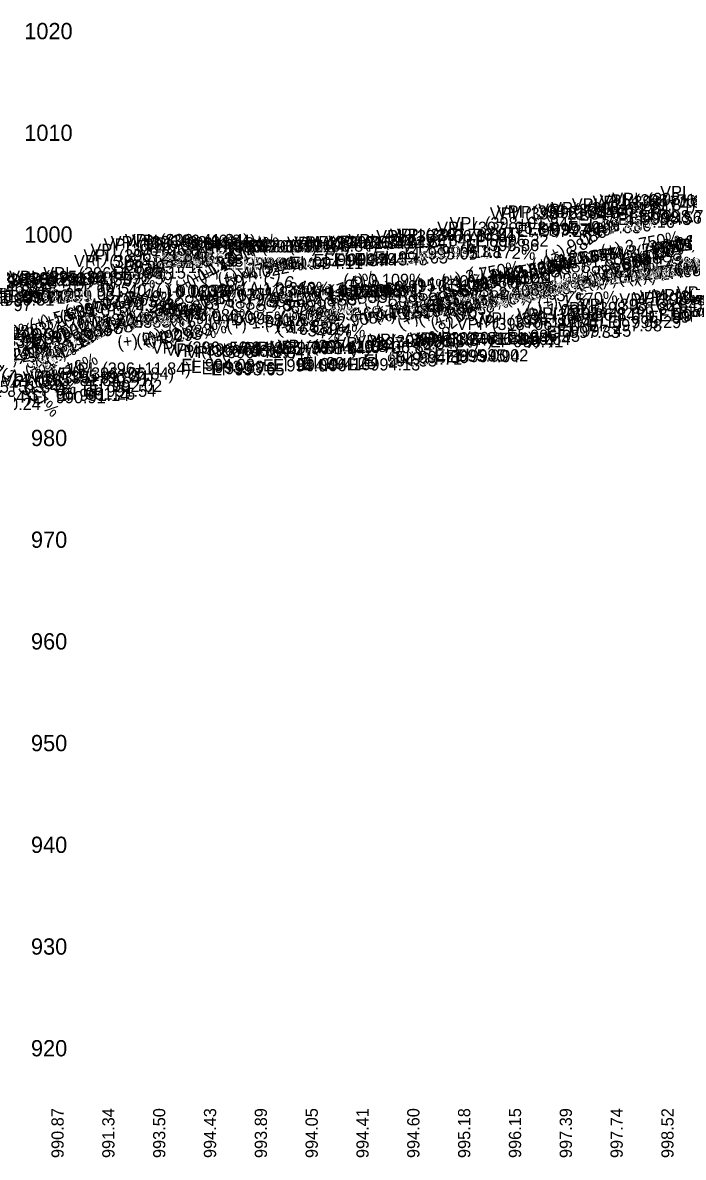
# Model space of a CAD drawing. Extents: x 16972137 to 16976737, y 12558490 to 12559551.
# Drawn here: x 16973948 to 16974273, y 12558490 to 12559047 of the extents above; entities that cross this region are included whole.
import ezdxf

# ---------------------------------------------------------------- set-up
doc = ezdxf.new("R2010")
doc.units = 0
for name, color, linetype in [('RD_DDB_ElevTX', 7, 'Continuous'), ('RD_DDB_GradeTX', 7, 'Continuous'), ('RD_DDB_PI', 7, 'Continuous'), ('RD_DDB_StripGrade_PR', 7, 'Continuous')]:
    doc.layers.add(name, color=color, linetype=linetype)

msp = doc.modelspace()

# ---------------------------------------------------------------- linework, layer by layer
at = {"layer": 'RD_DDB_PI'}
for centre in [(16974249.74, 12558929.2), (16974254.74, 12558930.1), (16974259.74, 12558930.78), (16974264.74, 12558931.47), (16974269.74, 12558932.13), (16974209.74, 12558924.04), (16974214.74, 12558925.66), (16974219.74, 12558926.59), (16974224.74, 12558926.3), (16974229.74, 12558925.95), (16974234.74, 12558926.55), (16974239.74, 12558927.44), (16974244.74, 12558928.33), (16974189.74, 12558918.63), (16974194.74, 12558920.9), (16974199.74, 12558921.35), (16974204.74, 12558922.52), (16974034.74, 12558912.59), (16974144.74, 12558912.55), (16974149.74, 12558912.88), (16974154.74, 12558913.61), (16974159.74, 12558914.54), (16974164.74, 12558915.19), (16974169.74, 12558915.22), (16974174.74, 12558914.3), (16974179.74, 12558914.03), (16974184.74, 12558914.42), (16974019.74, 12558907.85), (16974024.74, 12558910.39), (16974029.74, 12558911.58), (16974039.74, 12558912.25), (16974044.74, 12558910.98), (16974049.74, 12558909.7), (16974054.74, 12558908.78), (16974059.74, 12558908.14), (16974064.74, 12558907.56), (16974069.74, 12558909.49), (16974074.74, 12558909.53), (16974079.74, 12558909.53), (16974084.74, 12558909.51), (16974089.74, 12558909.49), (16974094.74, 12558909.6), (16974099.74, 12558909.86), (16974104.74, 12558910.11), (16974109.74, 12558910.58), (16974114.74, 12558911.18), (16974119.74, 12558911.49), (16974124.74, 12558911.57), (16974129.74, 12558909.97), (16974134.74, 12558911.69), (16974139.74, 12558911.94), (16974009.74, 12558902.26), (16974014.74, 12558905.08), (16973994.74, 12558896.3), (16973999.74, 12558897.02), (16974004.74, 12558899.44), (16973949.74, 12558891.86), (16973954.74, 12558892.88), (16973959.74, 12558893.18), (16973964.74, 12558893.48), (16973969.74, 12558893.76), (16973974.74, 12558893.85), (16973979.74, 12558894.47), (16973984.74, 12558895.01), (16973989.74, 12558895.58)]:
    msp.add_circle(centre, 1.75, dxfattribs=at)

# ---------------------------------------------------------------- texts
at = {"layer": 'RD_DDB_ElevTX'}
for s, p in [('1020', (16973948.52, 12559039.31)), ('1010', (16973948.52, 12558989.31)), ('1000', (16973948.52, 12558939.31)), ('990', (16973951.82, 12558889.31)), ('980', (16973951.82, 12558839.31)), ('970', (16973951.82, 12558789.31)), ('960', (16973951.82, 12558739.31)), ('950', (16973951.82, 12558689.31)), ('940', (16973951.82, 12558639.31)), ('930', (16973951.82, 12558589.31)), ('920', (16973951.82, 12558539.31))]:
    msp.add_text(s, height=8, dxfattribs=at).set_placement(p)
at = {"layer": 'RD_DDB_GradeTX'}
for s, rotation, p in [('(+) 16.821%', 40.0653, (16974205.12, 12558919.8)), ('(+) 9.086%', 24.4333, (16974206.01, 12558929.31)), ('(+) 11.072%', 28.9696, (16974030.11, 12558917.02)), ('(+) 10.173%', 26.9604, (16974035.47, 12558919.22)), ('(+) 3.750%', 10.6204, (16974232.74, 12558932.08)), ('(+) 3.015%', 8.5738, (16974250.25, 12558931.66)), ('(+) 2.996%', 8.5208, (16974254.14, 12558932.3)), ('(+) 3.526%', 9.9989, (16974257.4, 12558933.61)), ('(+) 2.942%', 8.3668, (16974258.77, 12558933.16)), ('(+) 3.508%', 9.9478, (16974262.53, 12558934.49)), ('(+) 2.854%', 8.1227, (16974263.74, 12558934.16)), ('(+) 2.766%', 7.8748, (16974269.24, 12558935.21)), ('(+) 11.289%', 29.4431, (16974024.86, 12558914.24)), ('(-) 1.172%', 356.6475, (16974162.39, 12558932.96)), ('(+) 2.753%', 7.8386, (16974198.59, 12558925.39)), ('(+) 2.665%', 7.5888, (16974203.8, 12558926.38)), ('(+) 2.645%', 7.5339, (16974208.8, 12558927.1)), ('(+) 6.467%', 17.9175, (16974231.2, 12558921.52)), ('(+) 2.795%', 7.9563, (16974234.02, 12558930.02)), ('(-) 5.082%', 345.742, (16973981.17, 12558930.23)), ('(+) 4.751%', 13.3624, (16974044.43, 12558918.15)), ('(+) 4.022%', 11.3718, (16974047.43, 12558918.2)), ('(+) 3.589%', 10.1734, (16974173.95, 12558918.69)), ('(+) 3.526%', 9.9989, (16974178.7, 12558919.73)), ('(+) 3.576%', 10.1379, (16974189.24, 12558921.43)), ('(+) 1.806%', 5.1588, (16974215.16, 12558925.75)), ('(+) 4.694%', 13.2093, (16974220.75, 12558917.04)), ('(+) 6.068%', 16.8769, (16974225.76, 12558919.49)), ('(-) 1.172%', 356.6475, (16974242.24, 12558928.28)), ('(-) 1.421%', 355.9359, (16974247.08, 12558927.72)), ('(+) 3.589%', 10.1734, (16974254.74, 12558920.99)), ('(+) 3.576%', 10.1379, (16974270.02, 12558923.69)), ('(-) 1.337%', 356.1754, (16973975.44, 12558919.56)), ('(+) 11.299%', 29.4638, (16974025.86, 12558901.03)), ('(-) 6.401%', 342.2536, (16974065.93, 12558920.94)), ('(+) 7.739%', 21.1528, (16974086.09, 12558906.17)), ('(+) 6.467%', 17.9175, (16974151.63, 12558908.4)), ('(+) 6.914%', 19.069, (16974152.53, 12558908.32)), ('(+) 3.750%', 10.6204, (16974154.2, 12558917.36)), ('(+) 1.316%', 3.766, (16974166.62, 12558917)), ('(-) 1.421%', 355.9359, (16974166.45, 12558921.42)), ('(+) 2.606%', 7.423, (16974178.19, 12558919.97)), ('(+) 2.625%', 7.4787, (16974215, 12558915.88)), ('(+) 2.671%', 7.6059, (16974222.32, 12558916.71)), ('(+) 2.704%', 7.6996, (16974225.71, 12558917.06)), ('(+) 2.728%', 7.7659, (16974230.38, 12558917.62)), ('(+) 2.776%', 7.9034, (16974241.07, 12558918.95)), ('(+) 2.889%', 8.2204, (16974245.59, 12558919.23)), ('(+) 2.408%', 6.8641, (16974249.56, 12558919.27)), ('(-) 5.149%', 345.5629, (16973985.29, 12558916.99)), ('(-) 1.337%', 356.1754, (16974055.25, 12558914.22)), ('(+) 0.313%', 0.8955, (16974059.76, 12558913.55)), ('(+) 2.606%', 7.423, (16974098.9, 12558909.64)), ('(+) 0.109%', 0.3115, (16974105.49, 12558917.87)), ('(-) 3.657%', 349.6382, (16974108.2, 12558917.32)), ('(+) 0.995%', 2.8486, (16974118.68, 12558913.81)), ('(+) 1.240%', 3.549, (16974135.05, 12558915.44)), ('(+) 0.313%', 0.8955, (16974139.75, 12558914.8)), ('(+) 0.998%', 2.857, (16974153.8, 12558915.65)), ('(+) 2.408%', 6.8641, (16974170.17, 12558909.71)), ('(+) 3.716%', 10.5244, (16974176.8, 12558908.55)), ('(+) 3.508%', 9.9478, (16974185.88, 12558908.87)), ('(+) 0.109%', 0.3115, (16974185.49, 12558918.3)), ('(-) 3.657%', 349.6382, (16974188.97, 12558914.75)), ('(+) 2.732%', 7.779, (16974195.09, 12558912.87)), ('(+) 4.751%', 13.3624, (16973966.73, 12558899.7)), ('(+) 4.022%', 11.3718, (16973969.09, 12558902.44)), ('(-) 3.654%', 349.6474, (16973988.02, 12558911.82)), ('(+) 0.160%', 0.4597, (16974010.49, 12558912.02)), ('(-) 0.023%', 359.9331, (16974013.21, 12558912.6)), ('(-) 0.055%', 359.8434, (16974018.51, 12558912.69)), ('(+) 9.676%', 25.818, (16974021.35, 12558897.47)), ('(+) 1.023%', 2.9289, (16974034.79, 12558909.54)), ('(+) 2.401%', 6.8459, (16974050.37, 12558906.47)), ('(+) 1.240%', 3.549, (16974055.21, 12558910.49)), ('(-) 5.082%', 345.742, (16974058.55, 12558910.57)), ('(-) 5.149%', 345.5629, (16974065.6, 12558908.71)), ('(+) 2.436%', 6.945, (16974078.57, 12558907.51)), ('(+) 0.160%', 0.4597, (16974090.48, 12558912.66)), ('(-) 0.023%', 359.9331, (16974093.21, 12558912.51)), ('(+) 3.716%', 10.5244, (16974096.04, 12558905.76)), ('(-) 0.055%', 359.8434, (16974098.51, 12558912.47)), ('(-) 0.086%', 359.7535, (16974103.87, 12558912.43)), ('(-) 1.097%', 356.8612, (16974115.41, 12558908.54)), ('(+) 2.401%', 6.8459, (16974131.2, 12558904.09)), ('(+) 9.086%', 24.4333, (16974133.62, 12558896.43)), ('(+) 1.806%', 5.1588, (16974136.58, 12558906.61)), ('(+) 2.436%', 6.945, (16974159.39, 12558905.27)), ('(+) 2.908%', 8.2731, (16974169.72, 12558906.69)), ('(+) 1.570%', 4.4896, (16974201.21, 12558906.69)), ('(+) 5.636%', 15.7391, (16973952.04, 12558895.75)), ('(+) 5.390%', 15.0828, (16973957.02, 12558896.93)), ('(+) 4.078%', 11.524, (16973968.16, 12558898.68)), ('(-) 2.589%', 352.6251, (16973992.89, 12558907.71)), ('(-) 2.314%', 353.401, (16973999.37, 12558906.06)), ('(+) 2.141%', 6.1104, (16974001.48, 12558899.81)), ('(+) 2.873%', 8.1736, (16974012.88, 12558901.94)), ('(+) 6.914%', 19.069, (16974073.28, 12558893.62)), ('(+) 1.023%', 2.9289, (16974115.29, 12558901.64)), ('(+) 1.570%', 4.4896, (16974121.47, 12558900.43)), ('(+) 1.881%', 5.372, (16974127.79, 12558903.24)), ('(+) 16.821%', 40.0653, (16974137.34, 12558878.48)), ('(+) 4.694%', 13.2093, (16974143, 12558898.79)), ('(-) 6.401%', 342.2536, (16974145.55, 12558908.06)), ('(+) 6.068%', 16.8769, (16974149.42, 12558896.33)), ('(-) 1.097%', 356.8612, (16974195.28, 12558904.16)), ('(+) 8.543%', 23.129, (16973950.47, 12558884.69)), ('(+) 11.072%', 28.9696, (16973960.75, 12558878.62)), ('(+) 10.173%', 26.9604, (16973964.71, 12558883.22)), ('(+) 1.204%', 3.4464, (16973975.06, 12558897.11)), ('(+) 1.192%', 3.4094, (16973981.71, 12558897.5)), ('(+) 1.123%', 3.2124, (16973986.31, 12558897.7)), ('(+) 0.338%', 0.9695, (16973988.09, 12558897.07)), ('(+) 7.739%', 21.1528, (16974007.49, 12558888.62)), ('(-) 0.086%', 359.7535, (16974023.82, 12558900.77)), ('(+) 0.450%', 1.2892, (16974028.96, 12558899.12)), ('(+) 0.995%', 2.8486, (16974039.38, 12558897.84)), ('(+) 1.881%', 5.372, (16974048.16, 12558895.75)), ('(-) 3.654%', 349.6474, (16974066.64, 12558897.46)), ('(-) 2.589%', 352.6251, (16974072.19, 12558897.45)), ('(+) 0.998%', 2.857, (16974074.5, 12558899.68)), ('(+) 1.316%', 3.766, (16974087.59, 12558899.77)), ('(+) 2.908%', 8.2731, (16974090.6, 12558895.19)), ('(+) 0.450%', 1.2892, (16974108.94, 12558900.92)), ('(-) 1.481%', 355.7651, (16973912.32, 12558894.42)), ('(+) 2.490%', 7.0961, (16973913.87, 12558889.29)), ('(-) 1.721%', 355.0806, (16973917.28, 12558893.79)), ('(-) 2.923%', 351.6863, (16973918.33, 12558892.6)), ('(-) 3.336%', 350.53, (16973923.21, 12558891.51)), ('(+) 2.883%', 8.2022, (16973928.46, 12558889.78)), ('(+) 7.990%', 21.7763, (16973946.21, 12558882.51)), ('(+) 11.299%', 29.4638, (16973950.95, 12558872.49)), ('(+) 11.289%', 29.4431, (16973955.84, 12558875.28)), ('(+) 5.397%', 15.102, (16973965.43, 12558886.77)), ('(+) 2.490%', 7.0961, (16973994.7, 12558887.26)), ('(+) 2.293%', 6.5394, (16974003.99, 12558888.15)), ('(+) 2.883%', 8.2022, (16974009.3, 12558889.3)), ('(-) 2.314%', 353.401, (16974078.81, 12558896.87)), ('(+) 2.141%', 6.1104, (16973923.24, 12558879.37)), ('(+) 2.293%', 6.5394, (16973924.55, 12558879.05)), ('(-) 7.737%', 338.8521, (16973929.09, 12558886.45)), ('(+) 2.873%', 8.1736, (16973935.45, 12558878.69)), ('(-) 16.557%', 320.3797, (16973930.29, 12558879.81)), ('(+) 9.676%', 25.818, (16973949.83, 12558862.87)), ('(-) 4.089%', 348.4452, (16973936.78, 12558871.98))]:
    msp.add_text(s, height=6, rotation=rotation, dxfattribs=at).set_placement(p)
at = {"layer": 'RD_DDB_PI'}
for s, p in [('VPI  (399+06.84)', (16974261.33, 12558961.18)), ('VPI  (398+51.84)', (16974207.63, 12558953.33)), ('VPI  (398+61.84)', (16974217.86, 12558955.1)), ('VPI  (398+71.84)', (16974228.04, 12558956.47)), ('VPI  (398+76.84)', (16974231.5, 12558957.13)), ('VPI  (398+81.84)', (16974237.74, 12558957.8)), ('VPI  (398+21.84)', (16974177.51, 12558950.66)), ('VPI  (398+26.84)', (16974180.97, 12558951.59)), ('VPI  (398+31.84)', (16974187.45, 12558951.3)), ('VPI  (398+46.84)', (16974201.33, 12558952.44)), ('El  998.43', (16974240.5, 12558947.97)), ('El  998.56', (16974245.65, 12558948.63)), ('El  998.70', (16974250.94, 12558949.3)), ('VPI  (397+96.84)', (16974151.62, 12558943.63)), ('VPI  (398+01.84)', (16974157.74, 12558945.9)), ('El  997.27', (16974191, 12558942.16)), ('El  997.46', (16974196.18, 12558943.09)), ('El  997.40', (16974201.06, 12558942.8)), ('El  997.63', (16974215.79, 12558943.94)), ('El  997.80', (16974220.94, 12558944.83)), ('El  998.16', (16974232.42, 12558946.6)), ('VPI  (396+36.84)', (16973991.03, 12558936.58)), ('VPI  (396+41.84)', (16973997.98, 12558937.59)), ('VPI  (396+46.84)', (16974001.44, 12558937.25)), ('VPI  (396+51.84)', (16974007.74, 12558935.98)), ('VPI  (397+21.84)', (16974077.8, 12558936.18)), ('VPI  (397+26.84)', (16974081.27, 12558936.49)), ('VPI  (397+31.84)', (16974087.74, 12558936.57)), ('VPI  (397+41.84)', (16974098.16, 12558936.69)), ('VPI  (397+51.84)', (16974107.92, 12558937.55)), ('VPI  (397+66.84)', (16974121.62, 12558939.54)), ('VPI  (397+71.84)', (16974128.33, 12558940.19)), ('VPI  (397+76.84)', (16974131.8, 12558940.22)), ('El  996.32', (16974170.26, 12558937.4)), ('VPI  (396+26.84)', (16973981.09, 12558932.85)), ('VPI  (396+31.84)', (16973987.57, 12558935.39)), ('VPI  (396+76.84)', (16974031.62, 12558934.49)), ('VPI  (396+81.84)', (16974037.86, 12558934.53)), ('VPI  (396+86.84)', (16974041.33, 12558934.53)), ('VPI  (396+91.84)', (16974047.98, 12558934.51)), ('VPI  (397+06.84)', (16974061.5, 12558934.86)), ('El  995.05', (16974135.44, 12558931.04)), ('El  995.18', (16974142.21, 12558931.69)), ('El  995.18', (16974147.21, 12558931.72)), ('El  995.86', (16974165.65, 12558935.13)), ('VPI  (396+16.84)', (16973972.98, 12558927.26)), ('VPI  (396+21.84)', (16973977.63, 12558930.08)), ('El  994.22', (16974000.32, 12558926.89)), ('El  994.45', (16974005.79, 12558928.08)), ('El  994.66', (16974011, 12558929.09)), ('El  994.59', (16974015.76, 12558928.75)), ('El  994.33', (16974020.2, 12558927.48)), ('El  994.04', (16974045.88, 12558925.99)), ('El  994.04', (16974050.88, 12558926.03)), ('El  994.04', (16974055.88, 12558926.03)), ('El  994.04', (16974060.88, 12558926.01)), ('El  994.11', (16974079.07, 12558926.36)), ('El  994.37', (16974090.76, 12558927.68)), ('El  994.44', (16974096, 12558927.99)), ('El  994.45', (16974100.79, 12558928.07)), ('El  994.48', (16974110.91, 12558928.19)), ('El  994.65', (16974120.79, 12558929.05)), ('VPI  (395+86.84)', (16973941.09, 12558919.47)), ('VPI  (396+01.84)', (16973957.86, 12558921.3)), ('El  993.15', (16973991.92, 12558921.58)), ('El  993.71', (16973997.3, 12558924.35)), ('VPI  (395+46.84)', (16973901.21, 12558914.17)), ('VPI  (395+56.84)', (16973910.97, 12558916.86)), ('VPI  (395+61.84)', (16973917.74, 12558917.88)), ('VPI  (395+66.84)', (16973921.21, 12558918.18)), ('VPI  (395+71.84)', (16973927.92, 12558918.48)), ('VPI  (395+76.84)', (16973931.39, 12558918.76)), ('El  992.59', (16973985.41, 12558918.76)), ('VPI  (395+41.84)', (16973897.74, 12558912.76)), ('El  990.51', (16973927.18, 12558908.36)), ('El  990.71', (16973932.6, 12558909.38)), ('El  990.77', (16973936.24, 12558909.68)), ('El  990.83', (16973940.38, 12558909.98)), ('El  990.89', (16973945.76, 12558910.26)), ('El  991.03', (16973957.03, 12558910.97)), ('El  991.40', (16973972.42, 12558912.8)), ('VPI  (398+86.84)', (16974241.21, 12558908.45)), ('VPI  (398+91.84)', (16974247.86, 12558909.12)), ('VPI  (398+96.84)', (16974251.33, 12558909.8)), ('VPI  (399+01.84)', (16974257.86, 12558910.48)), ('VPI  (399+11.84)', (16974269.51, 12558911.87)), ('El  989.97', (16973916.06, 12558905.67)), ('VPI  (398+56.84)', (16974211.09, 12558904.2)), ('VPI  (398+66.84)', (16974221.33, 12558905.78)), ('VPI  (398+11.84)', (16974169.4, 12558897.52)), ('VPI  (398+16.84)', (16974172.86, 12558899.04)), ('VPI  (398+36.84)', (16974190.91, 12558900.95)), ('VPI  (398+41.84)', (16974197.86, 12558901.55)), ('El  998.29', (16974235.53, 12558897.28)), ('El  998.83', (16974255.38, 12558899.95)), ('El  998.96', (16974260.88, 12558900.62)), ('El  999.10', (16974267.42, 12558901.3)), ('El  999.23', (16974270.26, 12558901.98)), ('VPI  (398+06.84)', (16974161.21, 12558896.35)), ('El  997.33', (16974205.38, 12558892.45)), ('El  997.45', (16974210.97, 12558893.05)), ('El  997.98', (16974226.09, 12558895.7)), ('VPI  (397+16.84)', (16974073.16, 12558885.58)), ('VPI  (397+46.84)', (16974101.62, 12558886.94)), ('VPI  (397+56.84)', (16974111.39, 12558887.88)), ('VPI  (397+61.84)', (16974118.16, 12558888.61)), ('VPI  (397+81.84)', (16974138.04, 12558889.3)), ('VPI  (397+86.84)', (16974141.5, 12558889.03)), ('VPI  (397+91.84)', (16974148.16, 12558889.42)), ('El  996.41', (16974177.54, 12558887.85)), ('El  996.64', (16974181, 12558889.02)), ('El  996.95', (16974185.79, 12558890.54)), ('VPI  (396+56.84)', (16974011.21, 12558884.7)), ('VPI  (396+61.84)', (16974017.98, 12558883.78)), ('VPI  (396+66.84)', (16974021.44, 12558883.14)), ('VPI  (396+71.84)', (16974028.16, 12558882.56)), ('VPI  (396+96.84)', (16974051.44, 12558884.49)), ('VPI  (397+01.84)', (16974058.04, 12558884.6)), ('VPI  (397+11.84)', (16974069.69, 12558885.11)), ('VPI  (397+36.84)', (16974091.21, 12558884.97)), ('El  994.86', (16974130.88, 12558880.11)), ('El  995.00', (16974150.53, 12558880.8)), ('El  994.94', (16974156, 12558880.53)), ('El  995.02', (16974160.32, 12558880.92)), ('VPI  (396+11.84)', (16973969.51, 12558874.44)), ('El  994.08', (16974025.79, 12558876.2)), ('El  993.89', (16974030.47, 12558875.28)), ('El  993.76', (16974035.76, 12558874.64)), ('El  994.04', (16974065.88, 12558875.99)), ('El  994.06', (16974070.88, 12558876.1)), ('El  994.16', (16974082.54, 12558876.61)), ('El  994.25', (16974085.44, 12558877.08)), ('El  994.13', (16974107.15, 12558876.47)), ('El  994.53', (16974115.38, 12558878.44)), ('El  994.71', (16974127.71, 12558879.38)), ('VPI  (395+81.84)', (16973937.63, 12558868.85)), ('VPI  (395+91.84)', (16973947.74, 12558870.01)), ('VPI  (395+96.84)', (16973951.21, 12558870.58)), ('VPI  (396+06.84)', (16973961.33, 12558872.02)), ('El  993.65', (16974040.38, 12558874.06)), ('VPI  (395+51.84)', (16973907.51, 12558865.51)), ('El  991.54', (16973977.3, 12558863.52)), ('El  992.02', (16973980.2, 12558865.94)), ('VPI  (395+36.84)', (16973890.79, 12558860.62)), ('El  990.91', (16973952.42, 12558860.35)), ('El  991.14', (16973964.07, 12558861.51)), ('El  991.25', (16973966.98, 12558862.08)), ('El  990.24', (16973920.53, 12558857.01))]:
    msp.add_text(s, height=6, dxfattribs=at).set_placement(p)
at = {"layer": 'RD_DDB_StripGrade_PR'}
for s, p in [('990.87', (16973967.9, 12558489.31)), ('991.34', (16973992.9, 12558489.31)), ('993.50', (16974017.9, 12558489.31)), ('994.43', (16974042.9, 12558489.31)), ('993.89', (16974067.9, 12558489.31)), ('994.05', (16974092.9, 12558489.31)), ('994.41', (16974117.9, 12558489.31)), ('994.60', (16974142.9, 12558489.31)), ('995.18', (16974167.9, 12558489.31)), ('996.15', (16974192.9, 12558489.31)), ('997.39', (16974217.9, 12558489.31)), ('997.74', (16974242.9, 12558489.31)), ('998.52', (16974267.9, 12558489.31))]:
    msp.add_text(s, height=6, rotation=90, dxfattribs=at).set_placement(p)

doc.saveas('drawing.dxf')
